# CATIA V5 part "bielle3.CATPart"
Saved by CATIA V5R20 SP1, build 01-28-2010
Part number: Part1.1.2.3
Bounding box of the stored display mesh (mm): x 55 to 87, y 0 to 10, z 28.093 to 41.907
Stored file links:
  E:\EDELI\gcausse\Edeli_2012_686_gcausse\bielle3.CATPart
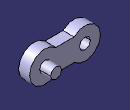
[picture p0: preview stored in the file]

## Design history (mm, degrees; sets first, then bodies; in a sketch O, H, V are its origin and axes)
Parameters
  long = 0.018
  diamtrou = 0.005
Body1 (main body)
  Sketch1 on zx-plane, origin (0, 0, 0), H (-1, 0, 0), V (0, 0, 1)
    line L1 (-66.899, 40) -> (-75.101, 40)
    line L2 (-66.899, 30) -> (-75.101, 30)
    arc A1 centre (-62, 35) radius 7 from (-66.899, 40) to (-66.899, 30) cw
    point P5 (-62, 35)
    point P6 (-57.101, 30)
    arc A2 centre (-80, 35) radius 7 from (-75.101, 40) to (-75.101, 30) ccw
    point P7 (-80, 35)
    circle A3 centre (-62, 35) radius 2.5
    distance P7 L1 = 5
    distance P5 L2 = 5
    distance L2 L1 = 10
    radius A1 = 7
    radius A2 = 7
    distance P5 P7 = 18 {= long}
    radius A3 = 2.5
    horizontal: L1 H, L2 H
    coincidence: A1 P6, P6 L2
  Pad1: profile Sketch1, direction (0, 1, 0), length 5
  Sketch2 on end face of Pad1, origin (0, 5, 0), H (-1, 0, 0), V (0, 0, 1)
    circle A1 centre (-80, 35) radius 2.5
    reference projected arc E1 centre (-80, 35) radius 7 from (-75.101, 40) to (-75.101, 30) ccw from edge [face of Pad1 from Sketch1.A2 | end face of Pad1]
    reference projected arc E2 centre (-80, 35) radius 7 from (-75.101, 40) to (-75.101, 30) ccw from edge [face of Pad1 from Sketch1.A2 | end face of Pad1]
    radius A1 = 2.5
    radius E2 = 7 (reference)
    concentricity: A1 E1
  Pad2: profile Sketch2, direction (0, 1, 0), length 5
